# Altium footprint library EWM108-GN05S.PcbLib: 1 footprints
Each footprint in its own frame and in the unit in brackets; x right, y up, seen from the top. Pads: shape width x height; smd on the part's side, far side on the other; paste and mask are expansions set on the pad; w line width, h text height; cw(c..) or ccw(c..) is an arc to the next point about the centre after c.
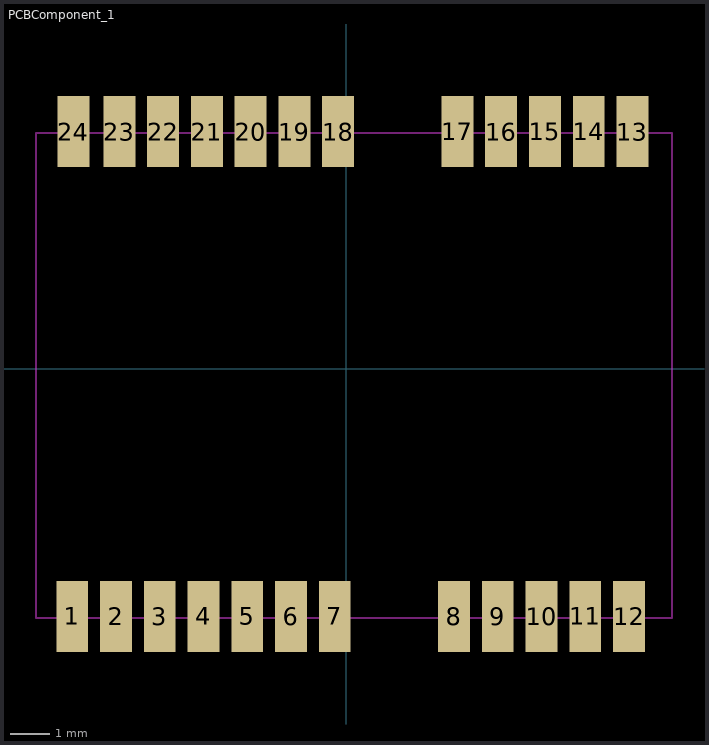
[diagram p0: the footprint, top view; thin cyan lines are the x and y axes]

## PCBComponent_1 [mil]
pads (24):
  rect 31.5x70 smd paste+0 mask+0: 1(-271.18,-245) 2(-227.87,-245) 3(-184.57,-245) 4(-141.26,-245) 5(-97.95,-245) 6(-54.65,-245) 7(-11.34,-245) 8(106.77,-245) 9(150.08,-245) 10(193.39,-245) 11(236.69,-245) 12(280,-245) 13(283.29,235) 14(239.99,235) 15(196.68,235) 16(153.37,235) 17(110.07,235) 18(-8.04,235) 19(-51.35,235) 20(-94.66,235) 21(-137.97,235) 22(-181.27,235) 23(-224.58,235) 24(-270,235)
Keep-Out Layer:
  lines w1.97: -307.26,-246.65 -307.26,233.67 ; -307.26,-246.65 -307.26,233.67 ; -307.26,-246.65 322.66,-246.65 ; -307.26,-246.65 322.66,-246.65 ; -307.26,233.67 322.66,233.67 ; -307.26,233.67 322.66,233.67 ; 322.66,-246.65 322.66,233.67 ; 322.66,-246.65 322.66,233.67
